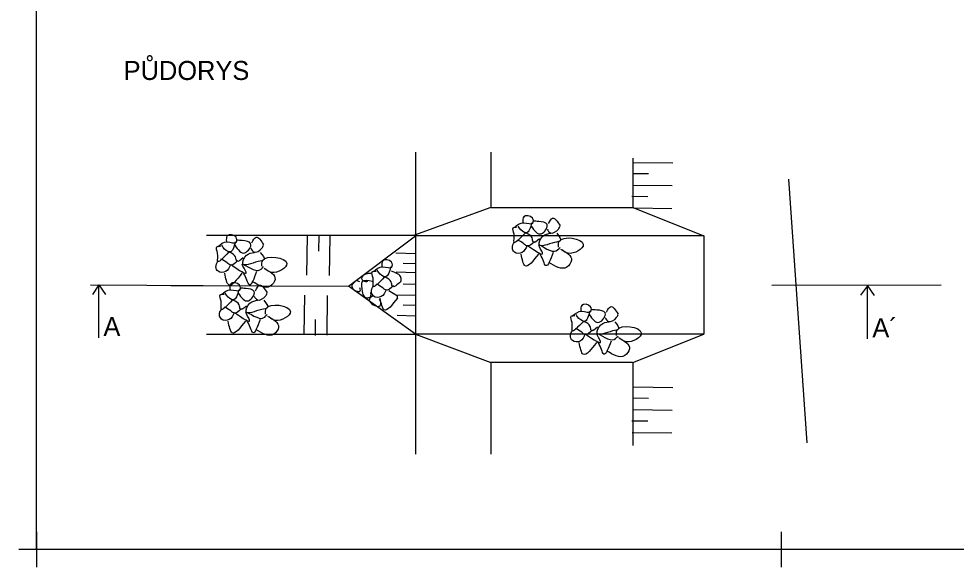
# Model space of a CAD drawing. Extents: x -463095.2 to -463015.6, y -1105044.4 to -1104976.7.
# Drawn here: x -463058.63 to -463032.2, y -1105037.13 to -1105021.66 of the extents above; entities that cross this region are included whole.
import ezdxf

# ---------------------------------------------------------------- set-up
doc = ezdxf.new("R2010")
doc.units = 0
doc.layers.add('Implicitní', color=7, linetype='Continuous')
doc.layers.add('Vrstva 14', color=7, linetype='Continuous')

msp = doc.modelspace()

# ---------------------------------------------------------------- linework, layer by layer
at = {"layer": 'Implicitní'}
for p, q in [((-463058.132, -1105036.132), (-463058.132, -1105037.132)), ((-463058.132, -1105036.132), (-463058.132, -1105037.132)), ((-463058.132, -1105036.132), (-463058.132, -1105037.132)), ((-463058.132, -1105036.132), (-463058.132, -1105037.132)), ((-463058.132, -1105036.132), (-463058.132, -1105037.132)), ((-463058.132, -1105036.132), (-463058.132, -1105037.132)), ((-463058.132, -1105036.132), (-463058.132, -1105037.132)), ((-463058.132, -1105036.132), (-463058.132, -1105037.132)), ((-463058.132, -1105036.132), (-463058.132, -1105037.132)), ((-463058.132, -1105036.132), (-463058.132, -1105037.132)), ((-463058.132, -1105036.132), (-463058.132, -1105037.132)), ((-463058.132, -1105036.132), (-463058.132, -1105037.132)), ((-463037.132, -1105036.132), (-463037.132, -1105037.132)), ((-463037.132, -1105036.132), (-463037.132, -1105037.132)), ((-463037.132, -1105036.132), (-463037.132, -1105037.132)), ((-463037.132, -1105036.132), (-463037.132, -1105037.132)), ((-463037.132, -1105036.132), (-463037.132, -1105037.132)), ((-463037.132, -1105036.132), (-463037.132, -1105037.132)), ((-463037.132, -1105036.132), (-463037.132, -1105037.132)), ((-463037.132, -1105036.132), (-463037.132, -1105037.132)), ((-463037.132, -1105036.132), (-463037.132, -1105037.132)), ((-463037.132, -1105036.132), (-463037.132, -1105037.132)), ((-463037.132, -1105036.132), (-463037.132, -1105037.132)), ((-463037.132, -1105036.132), (-463037.132, -1105037.132)), ((-463037.132, -1105036.132), (-463037.132, -1105037.132)), ((-463037.132, -1105036.132), (-463037.132, -1105037.132)), ((-463037.132, -1105036.132), (-463037.132, -1105037.132)), ((-463037.132, -1105036.132), (-463037.132, -1105037.132)), ((-463037.132, -1105036.132), (-463037.132, -1105037.132)), ((-463037.132, -1105036.132), (-463037.132, -1105037.132)), ((-463057.632, -1105036.632), (-463058.632, -1105036.632)), ((-463036.632, -1105036.632), (-463037.632, -1105036.632)), ((-463036.632, -1105036.632), (-463037.632, -1105036.632))]:
    msp.add_line(p, q, dxfattribs=at)
msp.add_lwpolyline([(-463058.132, -1104977.232), (-463016.132, -1104977.232), (-463016.132, -1105036.632), (-463058.132, -1105036.632)], close=True, dxfattribs=at)
at = {"layer": 'Vrstva 14'}
for p, q in [((-463047.441, -1105025.419), (-463047.441, -1105027.779)), ((-463045.319, -1105025.419), (-463045.319, -1105026.99)), ((-463041.319, -1105025.587), (-463041.319, -1105026.981)), ((-463040.19, -1105025.734), (-463041.3, -1105025.718)), ((-463040.874, -1105026.036), (-463041.326, -1105026.03)), ((-463047.443, -1105026.274), (-463047.443, -1105027.933)), ((-463040.205, -1105026.375), (-463041.315, -1105026.359)), ((-463036.926, -1105026.187), (-463036.404, -1105033.617)), ((-463040.889, -1105026.677), (-463041.341, -1105026.671)), ((-463045.319, -1105026.978), (-463047.471, -1105027.764)), ((-463040.215, -1105027.017), (-463041.293, -1105027.002)), ((-463050.506, -1105028.887), (-463050.49, -1105027.769)), ((-463050.166, -1105028.213), (-463050.16, -1105027.761)), ((-463049.864, -1105028.897), (-463049.848, -1105027.787)), ((-463039.317, -1105027.779), (-463047.441, -1105027.779)), ((-463039.317, -1105027.779), (-463039.317, -1105030.557)), ((-463047.994, -1105028.263), (-463047.445, -1105028.278)), ((-463047.986, -1105028.8), (-463047.441, -1105028.816)), ((-463047.795, -1105028.549), (-463047.441, -1105028.558)), ((-463056.608, -1105029.164), (-463053.43, -1105029.186)), ((-463054.339, -1105029.183), (-463049.334, -1105029.206)), ((-463047.795, -1105029.136), (-463047.441, -1105029.146)), ((-463034.702, -1105029.188), (-463034.513, -1105029.467)), ((-463050.573, -1105029.456), (-463050.589, -1105030.566)), ((-463049.931, -1105029.466), (-463049.947, -1105030.584)), ((-463047.99, -1105029.443), (-463047.441, -1105029.458)), ((-463047.795, -1105029.724), (-463047.441, -1105029.733)), ((-463047.958, -1105030.024), (-463047.445, -1105030.039)), ((-463050.271, -1105030.14), (-463050.277, -1105030.592)), ((-463047.441, -1105030.557), (-463047.441, -1105033.941)), ((-463047.441, -1105030.557), (-463045.319, -1105031.357)), ((-463045.319, -1105031.359), (-463045.319, -1105033.941)), ((-463041.319, -1105031.36), (-463041.319, -1105033.695)), ((-463040.19, -1105032.069), (-463041.3, -1105032.053)), ((-463040.874, -1105032.371), (-463041.326, -1105032.365)), ((-463040.205, -1105032.71), (-463041.315, -1105032.694)), ((-463040.889, -1105033.012), (-463041.341, -1105033.006)), ((-463040.215, -1105033.352), (-463041.333, -1105033.336))]:
    msp.add_line(p, q, dxfattribs=at)
for points in [[(-463045.319, -1105026.978), (-463041.318, -1105026.978), (-463039.317, -1105027.779)], [(-463053.336, -1105027.764), (-463047.471, -1105027.764)], [(-463056.37, -1105030.662), (-463056.37, -1105029.167), (-463056.552, -1105029.44)], [(-463056.37, -1105030.662), (-463056.37, -1105029.167), (-463056.189, -1105029.44)], [(-463047.953, -1105029.538), (-463047.953, -1105029.488), (-463048.192, -1105029.337)], [(-463037.394, -1105029.177), (-463032.625, -1105029.166)], [(-463034.697, -1105030.684), (-463034.702, -1105029.188), (-463034.892, -1105029.455)], [(-463053.336, -1105030.56), (-463047.441, -1105030.557)], [(-463039.317, -1105030.557), (-463047.441, -1105030.557)], [(-463041.319, -1105031.357), (-463039.317, -1105030.557)], [(-463041.329, -1105031.357), (-463045.332, -1105031.357)]]:
    msp.add_lwpolyline(points, dxfattribs=at)
msp.add_lwpolyline([(-463047.441, -1105030.557), (-463049.334, -1105029.206), (-463047.441, -1105027.779)], close=True, dxfattribs=at)
for points in [[(-463044.652, -1105027.543), (-463044.392, -1105027.413), (-463044.132, -1105027.413), (-463044.144, -1105027.283), (-463044.392, -1105027.247), (-463044.416, -1105027.401)], [(-463044.168, -1105027.413), (-463044.322, -1105027.697), (-463044.51, -1105027.567), (-463044.546, -1105027.507)], [(-463044.18, -1105027.507), (-463043.896, -1105027.721), (-463043.732, -1105027.461), (-463043.968, -1105027.377), (-463044.122, -1105027.365)], [(-463043.696, -1105027.437), (-463043.578, -1105027.283), (-463043.366, -1105027.495)], [(-463053.012, -1105028.082), (-463052.752, -1105027.952), (-463052.492, -1105027.952), (-463052.504, -1105027.822), (-463052.752, -1105027.786), (-463052.776, -1105027.94)], [(-463044.346, -1105027.697), (-463044.664, -1105027.957), (-463044.664, -1105027.733), (-463044.688, -1105027.555), (-463044.582, -1105027.531)], [(-463043.944, -1105027.863), (-463044.122, -1105027.957), (-463044.156, -1105027.839), (-463044.322, -1105027.709)], [(-463043.46, -1105027.709), (-463043.354, -1105027.911), (-463043.52, -1105027.969), (-463043.956, -1105028.029), (-463043.85, -1105027.791), (-463043.626, -1105027.709)], [(-463043.732, -1105027.591), (-463043.638, -1105027.697), (-463043.414, -1105027.591), (-463043.366, -1105027.507)], [(-463052.528, -1105027.952), (-463052.682, -1105028.236), (-463052.87, -1105028.106), (-463052.906, -1105028.046)], [(-463052.54, -1105028.046), (-463052.256, -1105028.26), (-463052.092, -1105028), (-463052.328, -1105027.916), (-463052.482, -1105027.904)], [(-463052.056, -1105027.976), (-463051.938, -1105027.822), (-463051.726, -1105028.034)], [(-463044.3, -1105028.059), (-463044.44, -1105028.253), (-463044.652, -1105028.241), (-463044.712, -1105028.123), (-463044.654, -1105027.953)], [(-463044.09, -1105027.941), (-463044.31, -1105028.065), (-463044.392, -1105028.005), (-463044.57, -1105027.899)], [(-463044.286, -1105028.053), (-463043.862, -1105028.265), (-463043.968, -1105028.053), (-463043.52, -1105028.217), (-463043.366, -1105028.111)], [(-463043.414, -1105028.099), (-463043.394, -1105027.943), (-463042.712, -1105028.021), (-463043.14, -1105028.275), (-463043.316, -1105028.177)], [(-463052.706, -1105028.236), (-463053.024, -1105028.496), (-463053.024, -1105028.272), (-463053.048, -1105028.094), (-463052.942, -1105028.07)], [(-463052.304, -1105028.402), (-463052.482, -1105028.496), (-463052.516, -1105028.378), (-463052.682, -1105028.248)], [(-463051.82, -1105028.248), (-463051.714, -1105028.45), (-463051.88, -1105028.508), (-463052.316, -1105028.568), (-463052.21, -1105028.33), (-463051.986, -1105028.248)], [(-463052.092, -1105028.13), (-463051.998, -1105028.236), (-463051.774, -1105028.13), (-463051.726, -1105028.046)], [(-463043.566, -1105028.253), (-463043.768, -1105028.621), (-463043.92, -1105028.313), (-463043.968, -1105028.253)], [(-463043.354, -1105028.157), (-463043.044, -1105028.471), (-463043.18, -1105028.665), (-463043.686, -1105028.529)], [(-463052.66, -1105028.598), (-463052.8, -1105028.792), (-463053.012, -1105028.78), (-463053.072, -1105028.662), (-463053.014, -1105028.492)], [(-463052.45, -1105028.48), (-463052.67, -1105028.604), (-463052.752, -1105028.544), (-463052.93, -1105028.438)], [(-463052.646, -1105028.592), (-463052.222, -1105028.804), (-463052.328, -1105028.592), (-463051.88, -1105028.756), (-463051.726, -1105028.65)], [(-463051.774, -1105028.638), (-463051.754, -1105028.482), (-463051.072, -1105028.56), (-463051.5, -1105028.814), (-463051.676, -1105028.716)], [(-463048.627, -1105028.786), (-463048.367, -1105028.656), (-463048.107, -1105028.656), (-463048.119, -1105028.526), (-463048.367, -1105028.49), (-463048.391, -1105028.644)], [(-463043.978, -1105028.295), (-463044.348, -1105028.627), (-463044.464, -1105028.295)], [(-463051.926, -1105028.792), (-463052.128, -1105029.16), (-463052.28, -1105028.852), (-463052.328, -1105028.792)], [(-463051.714, -1105028.696), (-463051.404, -1105029.01), (-463051.54, -1105029.204), (-463052.046, -1105029.068)], [(-463048.321, -1105028.94), (-463048.639, -1105029.2), (-463048.639, -1105028.976), (-463048.663, -1105028.798), (-463048.557, -1105028.774)], [(-463048.143, -1105028.656), (-463048.297, -1105028.94), (-463048.485, -1105028.81), (-463048.521, -1105028.75)], [(-463047.854, -1105029.072), (-463047.854, -1105028.96), (-463048.118, -1105028.779)], [(-463052.338, -1105028.834), (-463052.708, -1105029.166), (-463052.824, -1105028.834)], [(-463049.018, -1105029.081), (-463049.093, -1105029.049), (-463049.192, -1105029.118), (-463049.238, -1105029.187), (-463049.211, -1105029.273), (-463049.09, -1105029.346), (-463049.009, -1105029.346), (-463049.009, -1105029.246)], [(-463048.663, -1105029.073), (-463048.946, -1105029.073), (-463048.946, -1105029.355), (-463048.93, -1105029.432), (-463048.827, -1105029.528), (-463048.707, -1105029.489), (-463048.707, -1105029.384)], [(-463048.707, -1105028.845), (-463048.847, -1105028.863), (-463048.964, -1105028.985), (-463048.909, -1105029.05), (-463048.786, -1105029.063)], [(-463047.854, -1105029.072), (-463048.097, -1105029.2), (-463048.131, -1105029.082), (-463048.297, -1105028.952)], [(-463052.913, -1105029.435), (-463052.653, -1105029.305), (-463052.393, -1105029.305), (-463052.405, -1105029.175), (-463052.653, -1105029.139), (-463052.677, -1105029.293)], [(-463052.429, -1105029.305), (-463052.583, -1105029.589), (-463052.771, -1105029.459), (-463052.807, -1105029.399)], [(-463052.441, -1105029.399), (-463052.157, -1105029.613), (-463051.993, -1105029.353), (-463052.229, -1105029.269), (-463052.383, -1105029.257)], [(-463051.957, -1105029.329), (-463051.839, -1105029.175), (-463051.627, -1105029.387)], [(-463048.275, -1105029.302), (-463048.415, -1105029.496), (-463048.627, -1105029.484), (-463048.687, -1105029.366), (-463048.629, -1105029.196)], [(-463048.065, -1105029.184), (-463048.285, -1105029.308), (-463048.367, -1105029.248), (-463048.545, -1105029.142)], [(-463052.607, -1105029.589), (-463052.925, -1105029.849), (-463052.925, -1105029.625), (-463052.949, -1105029.447), (-463052.843, -1105029.423)], [(-463052.205, -1105029.755), (-463052.383, -1105029.849), (-463052.417, -1105029.731), (-463052.583, -1105029.601)], [(-463051.721, -1105029.601), (-463051.615, -1105029.803), (-463051.781, -1105029.861), (-463052.217, -1105029.921), (-463052.111, -1105029.683), (-463051.887, -1105029.601)], [(-463051.993, -1105029.483), (-463051.899, -1105029.589), (-463051.675, -1105029.483), (-463051.627, -1105029.399)], [(-463048.653, -1105029.481), (-463048.745, -1105029.567), (-463048.498, -1105029.774), (-463048.477, -1105029.774), (-463048.438, -1105029.609), (-463048.466, -1105029.58)], [(-463047.953, -1105029.538), (-463048.323, -1105029.87), (-463048.439, -1105029.538)], [(-463052.561, -1105029.951), (-463052.701, -1105030.145), (-463052.913, -1105030.133), (-463052.973, -1105030.015), (-463052.915, -1105029.845)], [(-463052.351, -1105029.833), (-463052.571, -1105029.957), (-463052.653, -1105029.897), (-463052.831, -1105029.791)], [(-463052.547, -1105029.945), (-463052.123, -1105030.157), (-463052.229, -1105029.945), (-463051.781, -1105030.109), (-463051.627, -1105030.003)], [(-463051.675, -1105029.991), (-463051.655, -1105029.835), (-463050.973, -1105029.913), (-463051.401, -1105030.167), (-463051.577, -1105030.069)], [(-463043.016, -1105030.04), (-463042.756, -1105029.91), (-463042.496, -1105029.91), (-463042.508, -1105029.78), (-463042.756, -1105029.744), (-463042.78, -1105029.898)], [(-463042.544, -1105030.004), (-463042.26, -1105030.218), (-463042.096, -1105029.958), (-463042.332, -1105029.874), (-463042.486, -1105029.862)], [(-463042.06, -1105029.934), (-463041.942, -1105029.78), (-463041.73, -1105029.992)], [(-463051.615, -1105030.049), (-463051.305, -1105030.363), (-463051.441, -1105030.557), (-463051.947, -1105030.421)], [(-463042.71, -1105030.194), (-463043.028, -1105030.454), (-463043.028, -1105030.23), (-463043.052, -1105030.052), (-463042.946, -1105030.028)], [(-463042.532, -1105029.91), (-463042.686, -1105030.194), (-463042.874, -1105030.064), (-463042.91, -1105030.004)], [(-463042.096, -1105030.088), (-463042.002, -1105030.194), (-463041.778, -1105030.088), (-463041.73, -1105030.004)], [(-463052.239, -1105030.187), (-463052.609, -1105030.519), (-463052.725, -1105030.187)], [(-463051.827, -1105030.145), (-463052.029, -1105030.513), (-463052.181, -1105030.205), (-463052.229, -1105030.145)], [(-463042.454, -1105030.438), (-463042.674, -1105030.562), (-463042.756, -1105030.502), (-463042.934, -1105030.396)], [(-463042.308, -1105030.36), (-463042.486, -1105030.454), (-463042.52, -1105030.336), (-463042.686, -1105030.206)], [(-463041.824, -1105030.206), (-463041.718, -1105030.408), (-463041.884, -1105030.466), (-463042.32, -1105030.526), (-463042.214, -1105030.288), (-463041.99, -1105030.206)], [(-463041.778, -1105030.596), (-463041.758, -1105030.44), (-463041.076, -1105030.518), (-463041.504, -1105030.772), (-463041.68, -1105030.674)], [(-463042.664, -1105030.556), (-463042.804, -1105030.75), (-463043.016, -1105030.738), (-463043.076, -1105030.62), (-463043.018, -1105030.45)], [(-463042.65, -1105030.55), (-463042.226, -1105030.762), (-463042.332, -1105030.55), (-463041.884, -1105030.714), (-463041.73, -1105030.608)], [(-463041.718, -1105030.654), (-463041.408, -1105030.968), (-463041.544, -1105031.162), (-463042.05, -1105031.026)], [(-463042.342, -1105030.792), (-463042.712, -1105031.124), (-463042.828, -1105030.792)], [(-463041.93, -1105030.75), (-463042.132, -1105031.118), (-463042.284, -1105030.81), (-463042.332, -1105030.75)]]:
    msp.add_spline(points, degree=3, dxfattribs=at)

# ---------------------------------------------------------------- texts
for s, p in [('PŮDORYS', (-463055.674, -1105023.384)), ('A', (-463056.244, -1105030.608))]:
    msp.add_text(s, height=0.536, dxfattribs=at).set_placement(p)
msp.add_text('A´', height=0.536, rotation=0.2805, dxfattribs=at).set_placement((-463034.561, -1105030.645))

doc.saveas('drawing.dxf')
